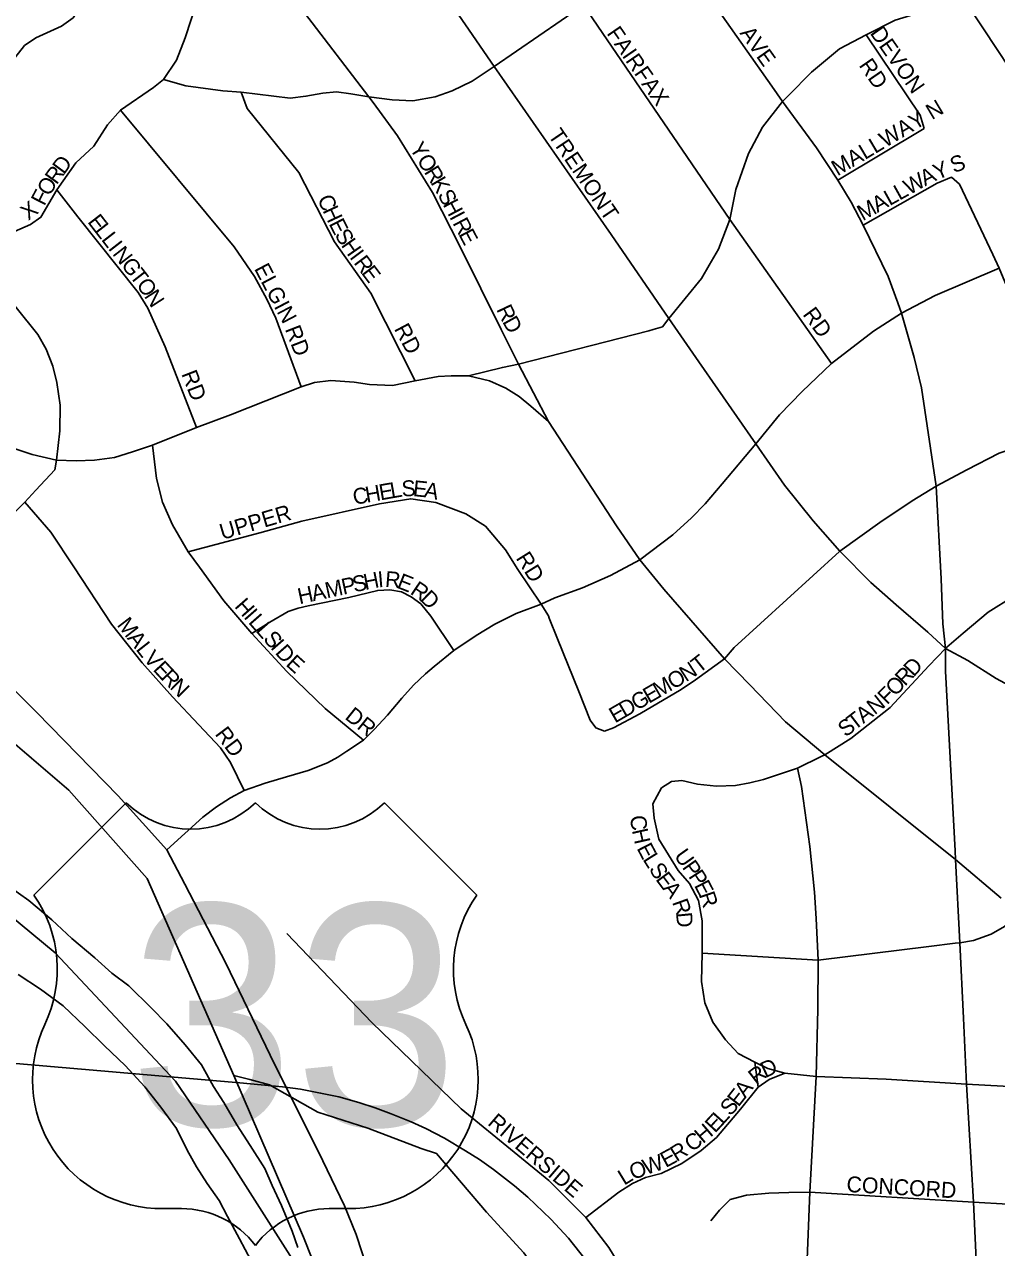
# Model space of a CAD drawing. Extents: x 0 to 34, y -6.2 to 22.
# Drawn here: x 2.952 to 3.531, y 19.984 to 20.712 of the extents above; entities that cross this region are included whole.
import ezdxf

# ---------------------------------------------------------------- set-up
doc = ezdxf.new("R2010")
doc.units = 0
for name, color, linetype in [('GM_X_City_Street', 7, 'Continuous'), ('GM_X_City_Street_Text', 7, 'Continuous'), ('GM_X_Corporation', 7, 'Continuous'), ('GM_X_Major_River', 7, 'Continuous'), ('GM_X_Rail_Line', 7, 'Continuous'), ('GM_X_Township', 7, 'Continuous'), ('GM_X_US_Route', 7, 'Continuous'), ('GM_X_US_Shield', 7, 'Continuous')]:
    doc.layers.add(name, color=color, linetype=linetype)

msp = doc.modelspace()

# ---------------------------------------------------------------- linework, layer by layer
at = {"layer": 'GM_X_City_Street'}
for points in [[(3.15966, 20.66606), (3.1572, 20.66944), (3.11893, 20.71948), (3.08935, 20.75804), (3.08273, 20.76982), (3.06841, 20.80306), (3.06492, 20.82044), (3.06366, 20.8323), (3.06285, 20.85371), (3.06639, 20.88108), (3.07551, 20.91758), (3.08317, 20.93672), (3.09347, 20.95144), (3.10436, 20.96115), (3.11496, 20.96792)], [(3.43258, 20.51062), (3.37218, 20.5964), (3.28496, 20.72404), (3.18943, 20.86166), (3.17942, 20.88049)], [(2.9198, 20.5892), (2.91392, 20.60523), (2.91013, 20.61509), (2.90833, 20.62125), (2.90751, 20.62742), (2.90849, 20.6363), (2.91079, 20.6432), (2.91704, 20.65454), (2.94628, 20.69269), (2.95218, 20.70005), (2.95894, 20.70447), (2.97425, 20.71153), (2.98102, 20.71653), (2.98456, 20.72154), (2.99928, 20.75274), (3.01693, 20.77894), (3.0293, 20.79748), (3.0343, 20.80308), (3.04843, 20.81161), (3.06492, 20.82044)], [(3.55937, 20.30749), (3.5306, 20.32294), (3.51371, 20.33364), (3.50048, 20.3409), (3.48997, 20.35061), (3.47108, 20.36684), (3.45612, 20.38015), (3.43754, 20.39873), (3.42169, 20.41687), (3.40461, 20.43821), (3.38756, 20.46268), (3.35369, 20.51151), (3.33578, 20.53732), (3.30142, 20.58731), (3.23167, 20.68754), (3.15087, 20.80543)], [(3.40699, 20.67017), (3.42073, 20.68413), (3.4374, 20.69788), (3.45319, 20.70636), (3.47044, 20.71513), (3.48624, 20.71981), (3.51343, 20.72449), (3.53975, 20.72683), (3.55584, 20.72888), (3.58768, 20.74116), (3.62185, 20.76781), (3.64944, 20.78818), (3.66763, 20.79634), (3.67609, 20.79916), (3.68863, 20.80135), (3.70766, 20.8019), (3.7703, 20.79828), (3.82389, 20.79532), (3.97378, 20.7856), (4.14593, 20.77512), (4.15248, 20.77439)], [(3.58568, 20.59383), (3.55788, 20.65723), (3.53156, 20.697), (3.51343, 20.72449), (3.49647, 20.74789), (3.46313, 20.7976), (3.46226, 20.79889)], [(2.92013, 20.58115), (2.92246, 20.58253), (2.93101, 20.58599), (2.94614, 20.58911), (2.95575, 20.59338), (2.96195, 20.59763), (2.97143, 20.61396), (2.98279, 20.62999), (2.99338, 20.64), (3.00163, 20.65266), (3.00928, 20.66149), (3.029, 20.67503), (3.03489, 20.67974), (3.04255, 20.69122), (3.04784, 20.70447), (3.0552, 20.72713), (3.05814, 20.73567), (3.06256, 20.7445), (3.06933, 20.75598), (3.07551, 20.76392), (3.08273, 20.76982)], [(3.39708, 20.67567), (3.36399, 20.72273), (3.35696, 20.73288)], [(3.03489, 20.67974), (3.04814, 20.67591), (3.07022, 20.67297), (3.0811, 20.67209), (3.11025, 20.66855), (3.11967, 20.66973), (3.12968, 20.6715), (3.13792, 20.67238), (3.14645, 20.6712), (3.1572, 20.66944), (3.17103, 20.66767), (3.1834, 20.66708), (3.19665, 20.66944), (3.2068, 20.67297), (3.21858, 20.67871), (3.23167, 20.68754), (3.28496, 20.72404)], [(3.4877, 20.65051), (3.48535, 20.6584), (3.45319, 20.70636)], [(3.18469, 20.50017), (3.15838, 20.55245), (3.13664, 20.58296), (3.11555, 20.6244), (3.08464, 20.66237), (3.0811, 20.67209)], [(3.47202, 20.54681), (3.46635, 20.56248), (3.45142, 20.5929), (3.44435, 20.60674), (3.4364, 20.61969), (3.42365, 20.6391), (3.40347, 20.66659), (3.39708, 20.67567)], [(3.2641, 20.476), (3.24634, 20.5102), (3.23598, 20.53091), (3.21165, 20.57974), (3.19503, 20.61233), (3.17413, 20.64618), (3.15966, 20.66606)], [(3.32653, 20.53086), (3.33199, 20.5324), (3.33578, 20.53732), (3.35518, 20.56117), (3.35986, 20.56914), (3.36537, 20.57876), (3.37218, 20.5964), (3.37569, 20.61424), (3.38329, 20.63559), (3.39148, 20.65138), (3.40347, 20.66659), (3.40699, 20.67017)], [(3.11679, 20.49672), (3.10183, 20.53765), (3.0964, 20.54883), (3.08901, 20.56231), (3.07695, 20.57999), (3.00928, 20.66149)], [(3.4364, 20.61969), (3.4877, 20.65051)], [(3.45142, 20.5929), (3.49559, 20.61805), (3.50407, 20.62155)], [(3.52868, 20.5754), (3.50875, 20.61746), (3.50407, 20.62155)], [(3.05448, 20.47238), (3.03591, 20.52056), (3.02555, 20.54357), (3.01977, 20.55287), (2.98384, 20.59796), (2.97143, 20.61396)], [(2.89336, 20.36891), (2.95239, 20.428), (2.95896, 20.43506), (2.97014, 20.44723), (2.97113, 20.45298), (2.97326, 20.47058), (2.97343, 20.4857), (2.97146, 20.49935), (2.96899, 20.50905), (2.96504, 20.51907), (2.96011, 20.52779), (2.94712, 20.5439), (2.93792, 20.5559), (2.92246, 20.58253), (2.91983, 20.58911), (2.9198, 20.5892)], [(3.50634, 20.16529), (3.50906, 20.16561), (3.51711, 20.16692), (3.52764, 20.1707), (3.53553, 20.17523), (3.54374, 20.18238), (3.55098, 20.19241), (3.5732, 20.24356), (3.58403, 20.29721), (3.588, 20.33077), (3.58731, 20.3892), (3.58494, 20.40208), (3.57223, 20.46068), (3.56977, 20.46934), (3.56585, 20.48313), (3.55548, 20.512), (3.53244, 20.56745), (3.52868, 20.5754)], [(3.03689, 20.22095), (3.0583, 20.24036), (3.06636, 20.24655), (3.07479, 20.25195), (3.08293, 20.25628), (3.09546, 20.26067), (3.10813, 20.26441), (3.12095, 20.26816), (3.13262, 20.27277), (3.13867, 20.27622), (3.14414, 20.27968), (3.15394, 20.28622), (3.16042, 20.29264), (3.16819, 20.30114), (3.17683, 20.31137), (3.18375, 20.319), (3.19081, 20.32577), (3.19599, 20.33023), (3.20766, 20.33974), (3.22105, 20.34853), (3.23214, 20.35529), (3.24496, 20.36163), (3.25982, 20.36733), (3.26786, 20.371), (3.28442, 20.37704), (3.30113, 20.38439), (3.31852, 20.39364), (3.33815, 20.40858), (3.34923, 20.41867), (3.35748, 20.42701), (3.36751, 20.43885), (3.38756, 20.46268), (3.40167, 20.48001), (3.41507, 20.49385), (3.43258, 20.51062), (3.45754, 20.52985), (3.47425, 20.54065), (3.49441, 20.55102), (3.53244, 20.56745)], [(3.50615, 20.22036), (3.50048, 20.32745), (3.50048, 20.3409), (3.49899, 20.35562), (3.49788, 20.38229), (3.49484, 20.43762), (3.48616, 20.49605), (3.48188, 20.51415), (3.47425, 20.54065), (3.47202, 20.54681)], [(3.21658, 20.50329), (3.23664, 20.50822), (3.24634, 20.5102), (3.32377, 20.53009), (3.32653, 20.53086)], [(3.53372, 20.19208), (3.50643, 20.21526), (3.42867, 20.27757), (3.40532, 20.29713), (3.38395, 20.31916), (3.36882, 20.33478), (3.33281, 20.37621), (3.31852, 20.39364), (3.3047, 20.41386), (3.2641, 20.476), (3.25358, 20.48521), (3.24667, 20.49096), (3.23878, 20.4959), (3.22908, 20.50033), (3.21658, 20.50329), (3.20623, 20.50329), (3.19834, 20.5028), (3.18469, 20.50017), (3.17121, 20.49754), (3.15756, 20.49803), (3.14835, 20.49951), (3.13455, 20.5005), (3.12485, 20.49935), (3.11679, 20.49672), (3.07486, 20.47995), (3.05448, 20.47238), (3.02834, 20.46186), (3.01634, 20.45792), (3.00565, 20.45463), (2.99381, 20.45292), (2.9828, 20.45259), (2.97113, 20.45298), (2.95666, 20.45644), (2.94597, 20.46006)], [(3.43735, 20.39856), (3.43754, 20.39873), (3.46143, 20.41584), (3.48056, 20.4288), (3.49484, 20.43762), (3.51324, 20.44734), (3.53244, 20.45725), (3.56977, 20.46934), (3.57071, 20.46964), (3.62074, 20.48438), (3.62836, 20.48589), (3.66062, 20.49572), (3.69028, 20.49943)], [(3.15394, 20.28622), (3.13109, 20.30512), (3.10824, 20.32715), (3.08752, 20.34984), (3.07075, 20.36924), (3.05629, 20.3893), (3.04954, 20.39834), (3.04034, 20.41445), (3.03425, 20.42793), (3.03069, 20.44219), (3.02834, 20.46186)], [(3.08293, 20.25628), (3.07897, 20.26435), (3.07486, 20.2729), (3.06878, 20.28178), (3.05596, 20.29542), (3.04017, 20.31203), (3.02225, 20.33241), (3.00384, 20.35527), (2.98156, 20.38959), (2.96788, 20.41008), (2.95239, 20.428)], [(3.04954, 20.39834), (3.09226, 20.40977), (3.11727, 20.41677), (3.16353, 20.42693), (3.18212, 20.43008), (3.19695, 20.42789), (3.21483, 20.42115), (3.22666, 20.41362), (3.23852, 20.39963), (3.24582, 20.38788), (3.25982, 20.36733), (3.2641, 20.36026), (3.26459, 20.35902)], [(3.29747, 20.29171), (3.30273, 20.29368), (3.31852, 20.3019), (3.34317, 20.31636), (3.35172, 20.32229), (3.36882, 20.33478), (3.37458, 20.34136), (3.43735, 20.39856)], [(3.50132, 20.34161), (3.5111, 20.34997), (3.52583, 20.36256), (3.54112, 20.3721), (3.55452, 20.379), (3.56825, 20.3846), (3.58731, 20.3892), (3.59833, 20.39133), (3.61036, 20.38929), (3.64423, 20.38738), (3.6467, 20.38724)], [(3.08752, 20.34984), (3.09821, 20.35658), (3.10914, 20.36293), (3.11505, 20.36494), (3.12106, 20.36628), (3.14515, 20.37128), (3.16243, 20.37546), (3.16963, 20.37589), (3.17655, 20.37459), (3.18245, 20.37157), (3.18807, 20.36739), (3.19398, 20.36005), (3.20766, 20.33974)], [(3.26459, 20.35902), (3.26952, 20.34662), (3.28218, 20.31521), (3.28892, 20.29811), (3.29221, 20.29368), (3.29747, 20.29171)], [(3.42652, 20.27652), (3.42867, 20.27757), (3.44412, 20.28727), (3.46747, 20.30568), (3.49066, 20.33054), (3.50048, 20.3409), (3.50132, 20.34161)], [(3.33134, 20.25784), (3.33726, 20.26162), (3.3435, 20.26228), (3.35287, 20.25998), (3.36406, 20.25883), (3.3754, 20.25932), (3.38395, 20.26088), (3.39217, 20.26277), (3.41239, 20.26967), (3.42652, 20.27652)], [(3.41738, 19.9572), (3.41962, 20.01715), (3.42357, 20.08603), (3.42455, 20.12599), (3.42472, 20.15525), (3.42357, 20.18007), (3.42242, 20.19569), (3.41962, 20.22298), (3.41469, 20.25866), (3.41239, 20.26967)], [(3.33134, 20.25784), (3.32615, 20.2483), (3.32704, 20.23982), (3.32972, 20.22732), (3.34133, 20.20856), (3.34803, 20.20098), (3.35338, 20.1907), (3.35562, 20.17865), (3.35562, 20.15946), (3.35517, 20.14249), (3.35718, 20.12976), (3.36187, 20.11838), (3.36946, 20.10789), (3.37705, 20.09962), (3.38687, 20.09449), (3.39468, 20.0907), (3.40473, 20.08802)], [(3.51991, 19.95122), (3.51711, 20.01123), (3.51301, 20.08143), (3.5112, 20.12073), (3.50906, 20.16561), (3.50643, 20.21526), (3.50615, 20.22036)], [(3.31285, 19.963), (3.29999, 19.98416), (3.2863, 20.00199), (3.26432, 20.02398), (3.24358, 20.04098), (3.21206, 20.0667), (3.15896, 20.11813), (3.10836, 20.17122)], [(3.35562, 20.15946), (3.42472, 20.15525), (3.49048, 20.16347), (3.50634, 20.16529)], [(3.38888, 20.07954), (3.38687, 20.09449)], [(3.2863, 20.00199), (3.30606, 20.01703), (3.31409, 20.02216), (3.32191, 20.02574), (3.33129, 20.02819), (3.34356, 20.03422), (3.35495, 20.04181), (3.3641, 20.04962), (3.37839, 20.06659), (3.38888, 20.07954), (3.39558, 20.08422), (3.40473, 20.08802)], [(3.40473, 20.08802), (3.42357, 20.08603), (3.46516, 20.08439), (3.51301, 20.08143), (3.55657, 20.07897), (3.62348, 20.07535)], [(3.36075, 20.00006), (3.36588, 20.00631), (3.37236, 20.01279), (3.38196, 20.01524), (3.39536, 20.01658), (3.40719, 20.0168), (3.41962, 20.01715), (3.51711, 20.01123), (3.53767, 20.00992), (3.64699, 20.0035)]]:
    msp.add_lwpolyline(points, dxfattribs=at)
at = {"layer": 'GM_X_Corporation'}
for points in [[(3.52818, 19.19521), (3.50428, 19.24388), (3.48313, 19.31343), (3.45707, 19.41938), (3.42241, 19.55281), (3.35451, 19.54623), (3.29812, 19.54245), (3.28941, 19.56547), (3.28201, 19.56559), (3.24174, 19.56624), (3.20171, 19.69807), (3.17374, 19.79814), (3.15602, 19.89513), (3.11815, 19.99031), (3.07685, 20.08662), (3.02508, 20.20382), (2.97862, 20.25643), (2.94372, 20.28635)], [(2.94372, 20.28635), (2.97862, 20.25643), (3.02508, 20.20382), (3.07685, 20.08662), (3.0863, 20.08412), (3.09795, 20.08105), (3.12677, 20.06473), (3.15659, 20.05511), (3.18832, 20.04308), (3.19745, 20.04019), (3.22726, 20.00509), (3.24938, 19.98105), (3.26, 19.96599), (3.31285, 19.963), (3.41738, 19.9572), (3.51991, 19.95122), (3.5666, 19.9481), (3.65077, 19.9435), (3.6922, 19.94158), (3.74012, 19.93873), (3.75089, 20.11953), (3.77081, 20.16721), (4.1276, 20.15181)], [(3.15602, 19.89513), (3.11815, 19.99031), (3.07685, 20.08662), (3.0863, 20.08412), (3.09795, 20.08105), (3.12677, 20.06473), (3.15659, 20.05511), (3.18832, 20.04308), (3.19745, 20.04019), (3.22726, 20.00509), (3.24938, 19.98105)]]:
    msp.add_lwpolyline(points, dxfattribs=at)
at = {"layer": 'GM_X_Major_River'}
for points in [[(3.11492, 19.98407), (3.11157, 19.99395), (3.10522, 20.00917), (3.09961, 20.02097), (3.09513, 20.03124), (3.08649, 20.04496), (3.07861, 20.05715), (3.07073, 20.07048), (3.06473, 20.08), (3.05761, 20.09295), (3.04783, 20.10477), (3.03691, 20.11736), (3.0275, 20.12691), (3.01432, 20.13989), (3.00413, 20.14754), (2.99396, 20.15671), (2.98039, 20.16818), (2.96833, 20.17926), (2.95476, 20.19073), (2.94231, 20.19953)], [(2.94844, 20.14675), (2.96165, 20.13794), (2.97523, 20.12799), (2.98803, 20.11577), (2.99971, 20.10431), (3.01214, 20.09247), (3.02381, 20.07988), (3.03321, 20.06768), (3.04261, 20.05509), (3.04897, 20.04215), (3.05459, 20.03225), (3.06098, 20.02235), (3.06811, 20.01206), (3.07298, 20.00254), (3.0801, 19.98922), (3.08685, 19.97665)]]:
    msp.add_lwpolyline(points, dxfattribs=at)
at = {"layer": 'GM_X_Rail_Line'}
for points in [[(2.27548, 20.27298), (2.33132, 20.24031), (2.36477, 20.22293), (2.39954, 20.20598), (2.43057, 20.19212), (2.45719, 20.18112), (2.52035, 20.15889), (2.55556, 20.14767), (2.59165, 20.13842), (2.6185, 20.13182), (2.65789, 20.12368), (2.68913, 20.11818), (2.72192, 20.11378), (2.82491, 20.10432), (3.08025, 20.08229), (3.10584, 20.07979)], [(3.10584, 20.07979), (3.11648, 20.0784), (3.12843, 20.07613), (3.13921, 20.07385), (3.15124, 20.07048), (3.16092, 20.0674), (3.1704, 20.06383), (3.18227, 20.05889), (3.19114, 20.05493), (3.20214, 20.04928), (3.21468, 20.0418), (3.22305, 20.03652), (3.23135, 20.0306), (3.2439, 20.02091), (3.25182, 20.01409), (3.26546, 20.00111), (3.27602, 19.98967), (3.29033, 19.97162)]]:
    msp.add_lwpolyline(points, dxfattribs=at)
at = {"layer": 'GM_X_Township'}
for points in [[(3.98086, 19.92295), (3.91113, 19.92982), (3.84238, 19.93372), (3.82109, 19.93456), (3.78172, 19.93611), (3.77505, 19.93689), (3.74012, 19.93873), (3.72287, 19.93964), (3.70934, 19.94079), (3.6922, 19.94158), (3.65077, 19.9435), (3.5666, 19.9481), (3.51991, 19.95122), (3.41738, 19.9572), (3.31285, 19.963), (3.26, 19.96599), (3.17216, 19.9709), (3.15674, 19.97007), (3.14349, 19.96662), (3.12409, 19.95776), (3.074, 20.0364), (3.04195, 20.08323), (2.97046, 20.15966), (2.92856, 20.19417)], [(2.92856, 20.19417), (2.97046, 20.15966), (3.04195, 20.08323), (3.074, 20.0364), (3.12409, 19.95776), (3.14349, 19.96662), (3.15674, 19.97007), (3.17216, 19.9709), (3.26, 19.96599), (3.31285, 19.963), (3.41738, 19.9572), (3.51991, 19.95122), (3.5666, 19.9481), (3.65077, 19.9435), (3.6922, 19.94158), (3.70934, 19.94079), (3.72287, 19.93964), (3.74012, 19.93873), (3.77505, 19.93689), (3.78172, 19.93611), (3.82109, 19.93456), (3.84238, 19.93372), (3.91113, 19.92982), (3.98086, 19.92295)]]:
    msp.add_lwpolyline(points, dxfattribs=at)
at = {"layer": 'GM_X_US_Route'}
for points in [[(2.80973, 20.46232), (2.82398, 20.44306), (2.85522, 20.40722), (2.87823, 20.38355), (2.89336, 20.36891), (2.90734, 20.3551), (2.95945, 20.30266), (3.00795, 20.25317), (3.03689, 20.22095), (3.04757, 20.20056), (3.07207, 20.15338), (3.09837, 20.09863), (3.11613, 20.06312), (3.11716, 20.06106)], [(3.11716, 20.06106), (3.12979, 20.03575), (3.14259, 20.00887), (3.14967, 19.99193), (3.15674, 19.97007), (3.16578, 19.93275), (3.18222, 19.86288), (3.19406, 19.81816), (3.21198, 19.75848), (3.22875, 19.70669), (3.2516, 19.64077), (3.28201, 19.56559), (3.28498, 19.55821)]]:
    msp.add_lwpolyline(points, dxfattribs=at)
at = {"layer": 'GM_X_US_Shield'}
for p, q in [((3.01267, 20.24898), (2.95774, 20.19405)), ((3.22141, 20.19405), (3.16648, 20.24898)), ((3.03465, 20.00728), (3.04563, 20.00728)), ((3.13352, 20.00728), (3.14451, 20.00728))]:
    msp.add_line(p, q, dxfattribs=at)
for centre, radius, start, end in [((3.05113, 20.28821), 0.05493, 225.573, 314.427), ((3.12803, 20.28821), 0.05493, 225.573, 314.427), ((2.89475, 20.14994), 0.0769, 334.54712, 35.00093), ((3.28441, 20.14994), 0.0769, 144.99907, 205.45288), ((3.03379, 20.08418), 0.0769, 154.83192, 270.63826), ((3.14537, 20.08418), 0.0769, 269.36174, 25.16808), ((3.04563, 19.95235), 0.05493, 36.8699, 90), ((3.13352, 19.95235), 0.05493, 90, 143.1301)]:
    msp.add_arc(centre, radius, start, end, dxfattribs=at)

# ---------------------------------------------------------------- texts
at = {"layer": 'GM_X_City_Street_Text'}
for s, rotation, p in [('FAIRFAX', 304.50911, (3.29845, 20.70722)), ('AVE', 305.31046, (3.3777, 20.70731)), ('DEVON', 304.99129, (3.4552, 20.7073)), ('RD', 304.51433, (3.4486, 20.68815)), ('MALLWAY N', 30.73649, (3.43617, 20.62198)), ('TREMONT', 304.16123, (3.26355, 20.64645)), ('Y', 301.47723, (3.1811, 20.63887)), ('O', 301.45858, (3.18545, 20.63177)), ('S', 21.36509, (3.50546, 20.62379)), ('R', 54.07263, (2.97121, 20.61663)), ('D', 53.61101, (2.9756, 20.62269)), ('R', 301.49526, (3.1898, 20.62465)), ('Y', 22.35754, (3.49547, 20.61972)), ('O', 57.74672, (2.96685, 20.60972)), ('K', 300.36028, (3.19369, 20.6183)), ('W', 29.12958, (3.47888, 20.61074)), ('A', 27.46435, (3.48827, 20.61597)), ('F', 62.7794, (2.96391, 20.60398)), ('S', 298.16569, (3.19786, 20.61119)), ('L', 29.10768, (3.46722, 20.60425)), ('L', 29.10768, (3.47305, 20.60749)), ('X', 37.47523, (2.95439, 20.59543)), ('C', 295.0177, (3.12627, 20.60853)), ('H', 297.75753, (3.201, 20.60533)), ('M', 29.10768, (3.45121, 20.59533)), ('A', 29.10768, (3.45994, 20.6002)), ('E', 307.75517, (2.98932, 20.59487)), ('H', 295.0177, (3.12944, 20.60174)), ('I', 297.73819, (3.20488, 20.59796)), ('L', 307.76403, (2.99341, 20.5896)), ('E', 296.99325, (3.13312, 20.59387)), ('R', 297.78173, (3.20682, 20.59426)), ('E', 297.76236, (3.21031, 20.58763)), ('L', 307.78135, (2.99749, 20.58433)), ('I', 307.77914, (3.00157, 20.57906)), ('S', 300.94435, (3.13649, 20.5873)), ('H', 304.89545, (3.14031, 20.58099)), ('N', 307.76187, (3.00412, 20.57577)), ('I', 306.87099, (3.14528, 20.57386)), ('G', 307.77935, (3.00923, 20.56918)), ('ELGIN', 297.75973, (3.08866, 20.5671)), ('R', 306.87099, (3.14778, 20.57053)), ('E', 306.87099, (3.15228, 20.56453)), ('T', 307.77677, (3.01433, 20.56259)), ('O', 305.38777, (3.01835, 20.5574)), ('N', 302.87179, (3.02312, 20.5507)), ('R', 295.5333, (3.23288, 20.54283)), ('RD', 306.2589, (3.41509, 20.53976)), ('RD', 291.24876, (3.10707, 20.53109)), ('RD', 297.90141, (3.17199, 20.53128)), ('D', 299.24057, (3.23641, 20.53548)), ('RD', 291.25285, (3.0454, 20.50442)), ('H', 9.79595, (3.15583, 20.42765)), ('E', 9.79525, (3.16404, 20.42906)), ('L', 9.79911, (3.17061, 20.4302)), ('S', 3.22529, (3.17689, 20.4313)), ('E', 353.868, (3.18314, 20.43169)), ('A', 348.7801, (3.18955, 20.43101)), ('C', 9.78571, (3.14843, 20.42637)), ('UPPER', 16.31505, (3.06991, 20.40549)), ('RD', 302.00293, (3.24442, 20.39472)), ('M', 12.20287, (3.13215, 20.37071)), ('P', 12.23924, (3.14193, 20.37283)), ('S', 12.22067, (3.14845, 20.37424)), ('H', 11.24134, (3.15492, 20.37564)), ('I', 4.90158, (3.16282, 20.37723)), ('R', 355.40575, (3.16656, 20.37758)), ('E', 338.45234, (3.17332, 20.37715)), ('R', 326.18195, (3.18122, 20.37372)), ('H', 12.22298, (3.11586, 20.36718)), ('A', 12.22298, (3.12401, 20.36895)), ('D', 315.60277, (3.18709, 20.36984)), ('H', 311.19621, (3.07677, 20.36577)), ('M', 307.61302, (3.00683, 20.35486)), ('I', 311.22251, (3.08226, 20.35949)), ('L', 311.19107, (3.08501, 20.35636)), ('L', 311.19107, (3.0894, 20.35134)), ('S', 311.19847, (3.09379, 20.34633)), ('A', 307.61938, (3.01293, 20.34694)), ('L', 307.94453, (3.01805, 20.34029)), ('I', 311.20333, (3.09818, 20.34131)), ('D', 311.22549, (3.10092, 20.33817)), ('V', 311.09763, (3.02251, 20.33459)), ('E', 317.75993, (3.10724, 20.33106)), ('T', 38.30554, (3.35372, 20.32576)), ('E', 312.78813, (3.02819, 20.32809)), ('R', 312.95518, (3.03274, 20.32318)), ('N', 32.89006, (3.34593, 20.32067)), ('R', 47.05364, (3.47637, 20.31804)), ('D', 47.03943, (3.48148, 20.32353)), ('N', 315.2379, (3.03815, 20.31739)), ('M', 30.10922, (3.32964, 20.31121)), ('O', 30.11099, (3.33829, 20.31622)), ('O', 46.97588, (3.47068, 20.31194)), ('G', 30.12649, (3.31667, 20.30368)), ('E', 30.11089, (3.32388, 20.30786)), ('F', 44.95821, (3.46571, 20.30697)), ('E', 30.11089, (3.30369, 20.29616)), ('D', 30.11099, (3.30946, 20.2995)), ('N', 38.49849, (3.45831, 20.301)), ('DR', 321.33664, (3.14236, 20.29934)), ('T', 37.54521, (3.44628, 20.29176)), ('A', 37.52994, (3.45157, 20.29582)), ('RD', 306.87427, (3.06517, 20.28984)), ('S', 37.54194, (3.441, 20.2877)), ('C', 277.40211, (3.31259, 20.24096)), ('H', 282.6852, (3.31372, 20.23258)), ('E', 297.34089, (3.31646, 20.22197)), ('U', 305.38777, (3.33851, 20.21734)), ('L', 302.18045, (3.31995, 20.21529)), ('S', 302.75697, (3.32355, 20.20956)), ('P', 305.37253, (3.34334, 20.21055)), ('E', 306.69466, (3.32757, 20.20337)), ('P', 302.73523, (3.34713, 20.20521)), ('A', 307.55444, (3.33164, 20.1979)), ('E', 297.54229, (3.35062, 20.19979)), ('R', 289.71754, (3.33763, 20.18983)), ('R', 288.94171, (3.35356, 20.19423)), ('D', 275.56053, (3.34002, 20.18337)), ('D', 25.0301, (3.39316, 20.08493)), ('R', 37.64707, (3.38769, 20.08063)), ('A', 51.84891, (3.3813, 20.07267)), ('E', 52.00931, (3.3772, 20.06742)), ('S', 48.80479, (3.37244, 20.06196)), ('RIVERSIDE', 319.39775, (3.22739, 20.05765)), ('E', 47.15784, (3.36325, 20.05189)), ('L', 48.00815, (3.36788, 20.05689)), ('C', 36.46264, (3.34943, 20.04074)), ('H', 40.44481, (3.35603, 20.04564)), ('R', 31.87805, (3.34032, 20.0349)), ('W', 18.84966, (3.32209, 20.02722)), ('E', 28.42893, (3.33392, 20.03142)), ('L', 31.38552, (3.30915, 20.0209)), ('O', 21.67152, (3.31446, 20.02419)), ('CONCORD', 356.63222, (3.44135, 20.01723))]:
    msp.add_text(s, height=0.00947, rotation=rotation, dxfattribs=at).set_placement(p)
at = {"layer": 'GM_X_US_Shield'}
msp.add_text('33', height=0.131836, dxfattribs=at).set_placement((3.01454, 20.05672))

doc.saveas('drawing.dxf')
